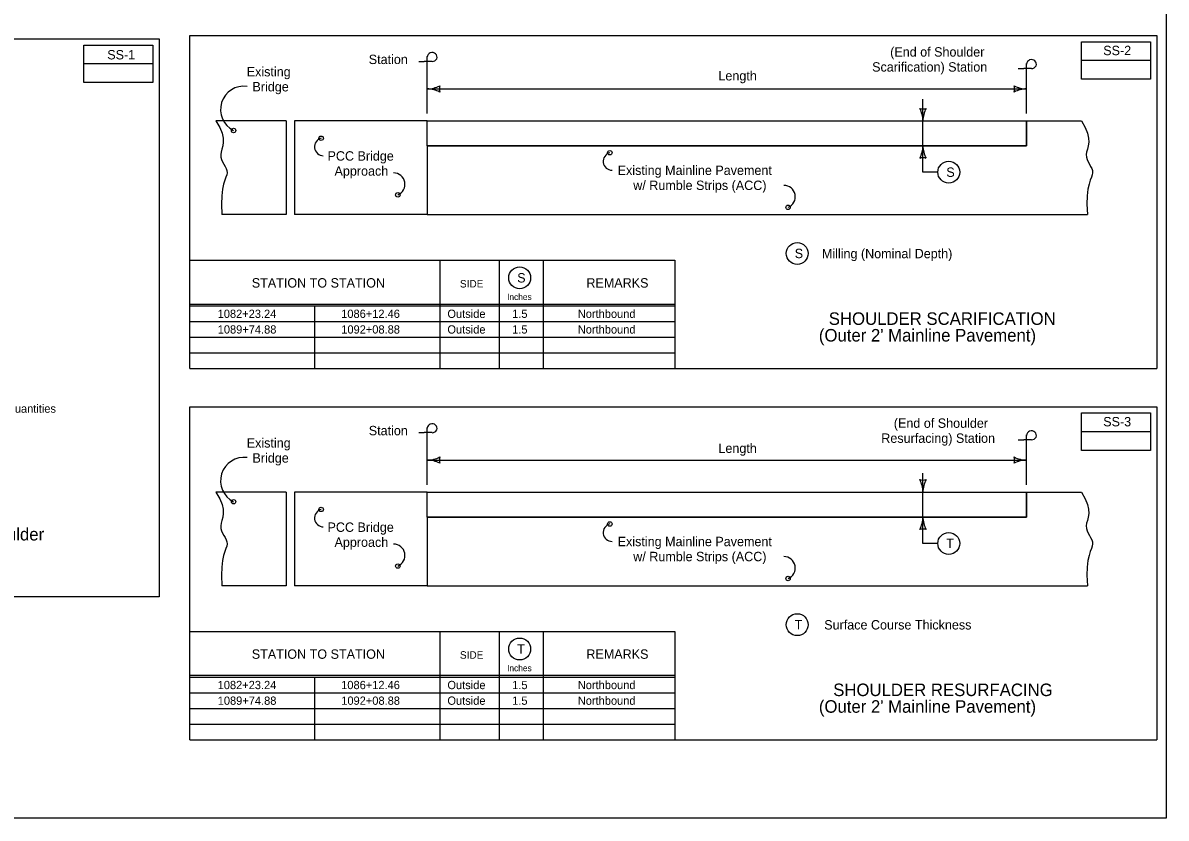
# Model space of a CAD drawing. Extents: x 10133 to 81668, y 7924 to 12229.
# Drawn here: x 15041 to 16868, y 7924 to 9195 of the extents above; entities that cross this region are included whole.
import ezdxf

# ---------------------------------------------------------------- set-up
doc = ezdxf.new("R2010")
doc.units = 0
for name, color, linetype in [('Default', 7, 'Continuous'), ('dsnCellsNorthArrow', 7, 'Continuous'), ('Level 11', 7, 'Continuous'), ('Level 14', 7, 'Continuous'), ('Level 2', 7, 'Continuous'), ('Level 20', 7, 'Continuous'), ('Level 22', 7, 'Continuous'), ('Level 4', 7, 'Continuous'), ('Level 5', 7, 'Continuous'), ('Level 6', 7, 'Continuous'), ('SheetBorder', 7, 'Continuous'), ('SheetText', 7, 'Continuous'), ('Text', 7, 'Continuous')]:
    doc.layers.add(name, color=color, linetype=linetype)

msp = doc.modelspace()

# ---------------------------------------------------------------- linework, layer by layer
at = {"layer": 'Default'}
for p, q in [((15687, 8405.1), (15687, 8444.9)), ((15687, 8444.9), (16644.6, 8444.9)), ((16644.6, 8444.9), (16644.6, 8405.1)), ((16644.6, 8405.1), (15687, 8405.1)), ((16644.6, 8405.1), (16644.6, 8405.1))]:
    msp.add_line(p, q, dxfattribs=at)
at = {"layer": 'Level 11'}
for p, q in [((15461.8, 9038), (15349.3, 9038)), ((15461.8, 9038), (15461.8, 8888.5)), ((15475, 9038), (15475, 8888.5)), ((15687, 9038), (15475, 9038)), ((15687, 8998.2), (15687, 9038)), ((15687, 9038), (16644.6, 9038)), ((16644.6, 8998.2), (16644.6, 9038)), ((16644.6, 9038), (16732.2, 9038)), ((15687, 8998.2), (16644.6, 8998.2)), ((15687, 8998.2), (15687, 8888.5)), ((15461.8, 8888.5), (15359, 8888.5)), ((15687, 8888.5), (15475, 8888.5)), ((15687, 8888.5), (16741.8, 8888.5)), ((15307.5, 8815.3), (16082.5, 8815.3)), ((15307.5, 8642.3), (15307.5, 8815.3)), ((15707.5, 8642.3), (15707.5, 8815.3)), ((15802.5, 8642.3), (15802.5, 8815.3)), ((15872.5, 8642.3), (15872.5, 8815.3)), ((16082.5, 8815.3), (16082.5, 8642.3)), ((15307.5, 8745.3), (16082.5, 8745.3)), ((15307.5, 8742.3), (16082.5, 8742.3)), ((15507.5, 8642.3), (15507.5, 8741.6)), ((15307.5, 8717.3), (16082.5, 8717.3)), ((15307.5, 8692.3), (16082.5, 8692.3)), ((15307.5, 8667.3), (16082.5, 8667.3)), ((15307.5, 8642.3), (16082.5, 8642.3)), ((15461.8, 8444.9), (15349.3, 8444.9)), ((15461.8, 8444.9), (15461.8, 8295.4)), ((15475, 8444.9), (15475, 8295.4)), ((15687, 8444.9), (15475, 8444.9)), ((15687, 8405.1), (15687, 8444.9)), ((15687, 8444.9), (16644.6, 8444.9)), ((16644.6, 8405.1), (16644.6, 8444.9)), ((16644.6, 8444.9), (16732.2, 8444.9)), ((15687, 8405.1), (16644.6, 8405.1)), ((15687, 8405.1), (15687, 8295.4)), ((15461.8, 8295.4), (15359, 8295.4)), ((15687, 8295.4), (15475, 8295.4)), ((15687, 8295.4), (16741.8, 8295.4)), ((15307.5, 8222.2), (16082.5, 8222.2)), ((15307.5, 8049.2), (15307.5, 8222.2)), ((15707.5, 8049.2), (15707.5, 8222.2)), ((15802.5, 8049.2), (15802.5, 8222.2)), ((15872.5, 8049.2), (15872.5, 8222.2)), ((16082.5, 8222.2), (16082.5, 8049.2)), ((15307.5, 8152.2), (16082.5, 8152.2)), ((15307.5, 8149.2), (16082.5, 8149.2)), ((15507.5, 8049.2), (15507.5, 8148.5)), ((15307.5, 8124.2), (16082.5, 8124.2)), ((15307.5, 8099.2), (16082.5, 8099.2)), ((15307.5, 8074.2), (16082.5, 8074.2)), ((15307.5, 8049.2), (16082.5, 8049.2))]:
    msp.add_line(p, q, dxfattribs=at)
msp.add_lwpolyline([(15687, 8998.2), (15687, 9038), (16644.6, 9038), (16644.6, 8998.2)], close=True, dxfattribs=at)
for centre in [(16520.2, 8956), (16278.1, 8826.2), (15834.6, 8787.3), (16520.2, 8362.9), (16278.1, 8233.1), (15834.6, 8194.2)]:
    msp.add_circle(centre, 17.5, dxfattribs=at)
for points in [[(15349.3, 9038), (15369.7, 9007.7), (15345.2, 8982.2), (15378.7, 8955.1), (15355.1, 8937.4), (15359, 8888.5)], [(16732.2, 9038), (16752.5, 9007.7), (16728.1, 8982.2), (16761.6, 8955.1), (16738, 8937.4), (16741.8, 8888.5)], [(15349.3, 8444.9), (15369.7, 8414.6), (15345.2, 8389.1), (15378.7, 8362), (15355.1, 8344.3), (15359, 8295.4)], [(16732.2, 8444.9), (16752.5, 8414.6), (16728.1, 8389.1), (16761.6, 8362), (16738, 8344.3), (16741.8, 8295.4)]]:
    msp.add_open_spline(points, degree=3, dxfattribs=at)
at = {"layer": 'Level 14'}
for p, q in [((15307.5, 8642.3), (16852.5, 8642.3)), ((15307.5, 8049.2), (16852.5, 8049.2))]:
    msp.add_line(p, q, dxfattribs=at)
msp.add_lwpolyline([(13745, 9169.2), (15258.4, 9169.2), (15258.4, 8277.8), (13745, 8277.8)], close=True, dxfattribs=at)
at = {"layer": 'Level 20'}
for p, q in [((15732.5, 8742.3), (15732.5, 8742.3)), ((15732.5, 8149.2), (15732.5, 8149.2))]:
    msp.add_line(p, q, dxfattribs=at)
at = {"layer": 'Level 22'}
for points in [[(15307.5, 9174.4), (16852.5, 9174.4), (16852.5, 8642.3)], [(15307.5, 8642.3), (15307.5, 9174.4)], [(16842.5, 9164.4), (16842.5, 9104.4), (16732.5, 9104.4), (16732.5, 9164.4), (16842.5, 9164.4), (16842.5, 9134.4), (16732.5, 9134.4)], [(15307.5, 8581.3), (16852.5, 8581.3), (16852.5, 8049.2)], [(15307.5, 8049.2), (15307.5, 8581.3)], [(16842.5, 8571.3), (16842.5, 8511.3), (16732.5, 8511.3), (16732.5, 8571.3), (16842.5, 8571.3), (16842.5, 8541.3), (16732.5, 8541.3)]]:
    msp.add_lwpolyline(points, dxfattribs=at)
at = {"layer": 'Level 4'}
for centre in [(15377.5, 9022.6), (15517.4, 9010.3), (15978.7, 8987.1), (15640, 8919.8), (16263.5, 8899.9), (15377.5, 8429.5), (15517.4, 8417.2), (15517.4, 8417.2), (15978.7, 8394), (15978.7, 8394), (15640, 8326.7), (15640, 8326.7), (16263.5, 8306.8), (16263.5, 8306.8)]:
    msp.add_circle(centre, 3.54, dxfattribs=at)
at = {"layer": 'Level 5'}
for p, q in [((15687, 9089.1), (16644.6, 9089.1)), ((16644.6, 9089.1), (16644.6, 9089.1)), ((16478.9, 9038), (16478.9, 9038)), ((16478.9, 8998.2), (16478.9, 8998.2)), ((15687, 8496), (16644.6, 8496)), ((16644.6, 8496), (16644.6, 8496)), ((16478.9, 8444.9), (16478.9, 8444.9)), ((16478.9, 8405.1), (16478.9, 8405.1))]:
    msp.add_line(p, q, dxfattribs=at)
for centre, radius, start, end in [((15394.1, 9056.1), 37.4, 82.1557, 243.5963), ((15687, 9131.6), 42.5, 270, 298.0725), ((15687, 9046.6), 42.5, 61.9275, 90), ((15722.7, 9089.1), 16.4, 162.2666, 197.7334), ((16609, 9089.1), 16.4, 342.2666, 17.7333), ((16644.6, 9131.6), 42.5, 241.9275, 270), ((16644.6, 9046.6), 42.5, 90, 118.0725), ((16478.9, 9073.6), 16.4, 252.2666, 287.7333), ((16436.4, 9038), 42.5, 360, 28.0725), ((16521.4, 9038), 42.5, 151.9275, 180), ((15521, 8996.6), 14.2, 104.4485, 269.6713), ((16436.4, 8998.2), 42.5, 331.9275, 360), ((16521.4, 8998.2), 42.5, 180, 208.0725), ((15982.3, 8973.3), 14.2, 104.4485, 269.6713), ((16478.9, 8962.5), 16.4, 72.2666, 107.7334), ((15633.2, 8936.7), 18.2, 291.7324, 90.5685), ((16256.8, 8916.8), 18.2, 291.7324, 90.5685), ((15394.1, 8463), 37.4, 82.1557, 243.5963), ((15687, 8538.5), 42.5, 270, 298.0725), ((15687, 8453.5), 42.5, 61.9275, 90), ((15722.7, 8496), 16.4, 162.2666, 197.7334), ((16609, 8496), 16.4, 342.2666, 17.7333), ((16644.6, 8538.5), 42.5, 241.9275, 270), ((16644.6, 8453.5), 42.5, 90, 118.0725), ((16478.9, 8480.5), 16.4, 252.2666, 287.7333), ((16436.4, 8444.9), 42.5, 360, 28.0725), ((16521.4, 8444.9), 42.5, 151.9275, 180), ((15521, 8403.5), 14.2, 104.4485, 269.6713), ((15521, 8403.5), 14.2, 104.4485, 269.6713), ((16436.4, 8405.1), 42.5, 331.9275, 360), ((16521.4, 8405.1), 42.5, 180, 208.0725), ((15982.3, 8380.2), 14.2, 104.4485, 269.6713), ((15982.3, 8380.2), 14.2, 104.4485, 269.6713), ((16478.9, 8369.4), 16.4, 72.2666, 107.7334), ((15633.2, 8343.6), 18.2, 291.7324, 90.5685), ((15633.2, 8343.6), 18.2, 291.7324, 90.5685), ((16256.8, 8323.7), 18.2, 291.7324, 90.5685), ((16256.8, 8323.7), 18.2, 291.7324, 90.5685)]:
    msp.add_arc(centre, radius, start, end, dxfattribs=at)
at = {"layer": 'Level 6'}
for p, q in [((15687, 9117.1), (15687, 9141)), ((15673.7, 9133), (15682.3, 9133)), ((15694.8, 9133), (15682.3, 9133)), ((15687, 9049.7), (15687, 9117.1)), ((16631.3, 9121.5), (16639.9, 9121.5)), ((16652.4, 9121.5), (16639.9, 9121.5)), ((16644.6, 9105.7), (16644.6, 9129.5)), ((16644.6, 9049.7), (16644.6, 9105.7)), ((16478.9, 8956), (16478.9, 9072.9)), ((16502.7, 8956), (16478.9, 8956)), ((15673.7, 8539.9), (15682.3, 8539.9)), ((15694.8, 8539.9), (15682.3, 8539.9)), ((15687, 8524), (15687, 8547.9)), ((16644.6, 8512.6), (16644.6, 8536.4)), ((15687, 8456.6), (15687, 8524)), ((16631.3, 8528.4), (16639.9, 8528.4)), ((16652.4, 8528.4), (16639.9, 8528.4)), ((16644.6, 8456.6), (16644.6, 8512.6)), ((16478.9, 8362.9), (16478.9, 8475)), ((16502.7, 8362.9), (16478.9, 8362.9))]:
    msp.add_line(p, q, dxfattribs=at)
for centre in [(15694.8, 9140.1), (16652.4, 9128.7), (15694.8, 8547), (16652.4, 8535.6)]:
    msp.add_ellipse(centre, major_axis=(-7.81, 0), ratio=0.913811, start_param=1.570796, end_param=6.283185, dxfattribs=at)
at = {"layer": 'SheetBorder'}
msp.add_lwpolyline([(13732.5, 9944), (16867.5, 9944), (16867.5, 7924), (13732.5, 7924)], close=True, dxfattribs=at)
at = {"layer": 'Text'}
msp.add_lwpolyline([(15248.4, 9159.2), (15248.4, 9099.2), (15138.4, 9099.2), (15138.4, 9159.2), (15248.4, 9159.2), (15248.4, 9129.2), (15138.4, 9129.2)], dxfattribs=at)

# ---------------------------------------------------------------- texts
at = {"layer": 'dsnCellsNorthArrow'}
for s, p in [('SS-2', (16767, 9143)), ('SS-3', (16767, 8549.9))]:
    msp.add_text(s, height=15, dxfattribs=at).set_placement(p)
at = {"layer": 'Level 2'}
for s, height, p in [('(End of Shoulder', 15, (16426.6, 9140.7)), ('Station', 15, (15593.5, 9128.8)), ('Existing', 15, (15398.5, 9109.1)), ('Length', 15, (16152.2, 9102.6)), ('Scarification) Station', 15, (16397.8, 9116.7)), ('Bridge', 15, (15407.7, 9085.1)), ('PCC Bridge', 15, (15527.6, 8974.5)), ('Approach', 15, (15538.8, 8950.5)), ('Existing Mainline Pavement', 15, (15991.2, 8951.6)), ('S', 15, (16516.3, 8948.5)), ('w/ Rumble Strips (ACC)', 15, (16016.1, 8927.6)), ('S', 15, (16274.1, 8818.7)), ('Milling (Nominal Depth)', 15, (16317.5, 8818.5)), ('STATION TO STATION', 15, (15406.6, 8771.7)), ('S', 15, (15830.7, 8779.8)), ('REMARKS', 15, (15941.2, 8771.7)), ('SIDE', 12, (15739.2, 8771.8)), ('Inches', 10, (15814.5, 8751.8)), ('SHOULDER SCARIFICATION', 20, (16328.5, 8712.1)), ("(Outer 2' Mainline Pavement)", 20, (16312.7, 8685.5)), ('Station', 15, (15593.5, 8535.7)), ('(End of Shoulder', 15, (16432.4, 8547.6)), ('Existing', 15, (15398.5, 8516)), ('Resurfacing) Station', 15, (16412.4, 8523.6)), ('Length', 15, (16152.2, 8507.5)), ('Bridge', 15, (15407.7, 8492)), ('PCC Bridge', 15, (15527.6, 8381.4)), ('PCC Bridge', 15, (15527.6, 8381.4)), ('Approach', 15, (15538.8, 8357.4)), ('Approach', 15, (15538.8, 8357.4)), ('Existing Mainline Pavement', 15, (15991.2, 8358.5)), ('T', 15, (16516.2, 8355.4)), ('w/ Rumble Strips (ACC)', 15, (16016.1, 8334.5)), ('T', 15, (16274.1, 8225.6)), ('Surface Course Thickness', 15, (16321.2, 8225.4)), ('STATION TO STATION', 15, (15406.6, 8178.6)), ('SIDE', 12, (15739.2, 8178.7)), ('T', 15, (15830.6, 8186.7)), ('REMARKS', 15, (15941.2, 8178.6)), ('Inches', 10, (15814.5, 8158.7)), ('SHOULDER RESURFACING', 20, (16335.6, 8119)), ("(Outer 2' Mainline Pavement)", 20, (16312.7, 8092.4))]:
    msp.add_text(s, height=height, dxfattribs=at).set_placement(p)
at = {"layer": 'SheetText'}
for s, height, p in [('SS-1', 15, (15175.7, 9136.2)), ('1082+23.24', 13.2, (15352.1, 8723.2)), ('1086+12.46', 13.2, (15549.5, 8723.2)), ('Outside', 13.2, (15719.2, 8723.2)), ('1.5', 13.2, (15822.6, 8723.2)), ('Northbound', 13.2, (15927.5, 8723.2)), ('1089+74.88', 13.2, (15352.2, 8698.2)), ('1092+08.88', 13.2, (15549.6, 8698.2)), ('Outside', 13.2, (15719.2, 8698.2)), ('1.5', 13.2, (15822.6, 8698.2)), ('Northbound', 13.2, (15927.5, 8698.2)), ('Refer to Tab. 112-9 for P width and Shoulder quantities', 13.2, (14662, 8571.7)), ('HMA Paved Shoulder', 20, (14817.7, 8367.6)), ('1082+23.24', 13.2, (15352.1, 8130.1)), ('1086+12.46', 13.2, (15549.5, 8130.1)), ('Outside', 13.2, (15719.2, 8130.1)), ('1.5', 13.2, (15822.6, 8130.1)), ('Northbound', 13.2, (15927.5, 8130.1)), ('1089+74.88', 13.2, (15352.2, 8105.1)), ('1092+08.88', 13.2, (15549.6, 8105.1)), ('Outside', 13.2, (15719.2, 8105.1)), ('1.5', 13.2, (15822.6, 8105.1)), ('Northbound', 13.2, (15927.5, 8105.1))]:
    msp.add_text(s, height=height, dxfattribs=at).set_placement(p)

doc.saveas('drawing.dxf')
